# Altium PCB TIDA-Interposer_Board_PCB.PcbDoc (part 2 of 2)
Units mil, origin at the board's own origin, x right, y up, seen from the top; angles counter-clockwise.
Board outline 4000 x 3600 mil, 4 copper layers (Top Layer, GND, PWR, Bottom Layer), stack 5.48 mil thick; 55 components, 24 nets, 133 pads, 140 vias.
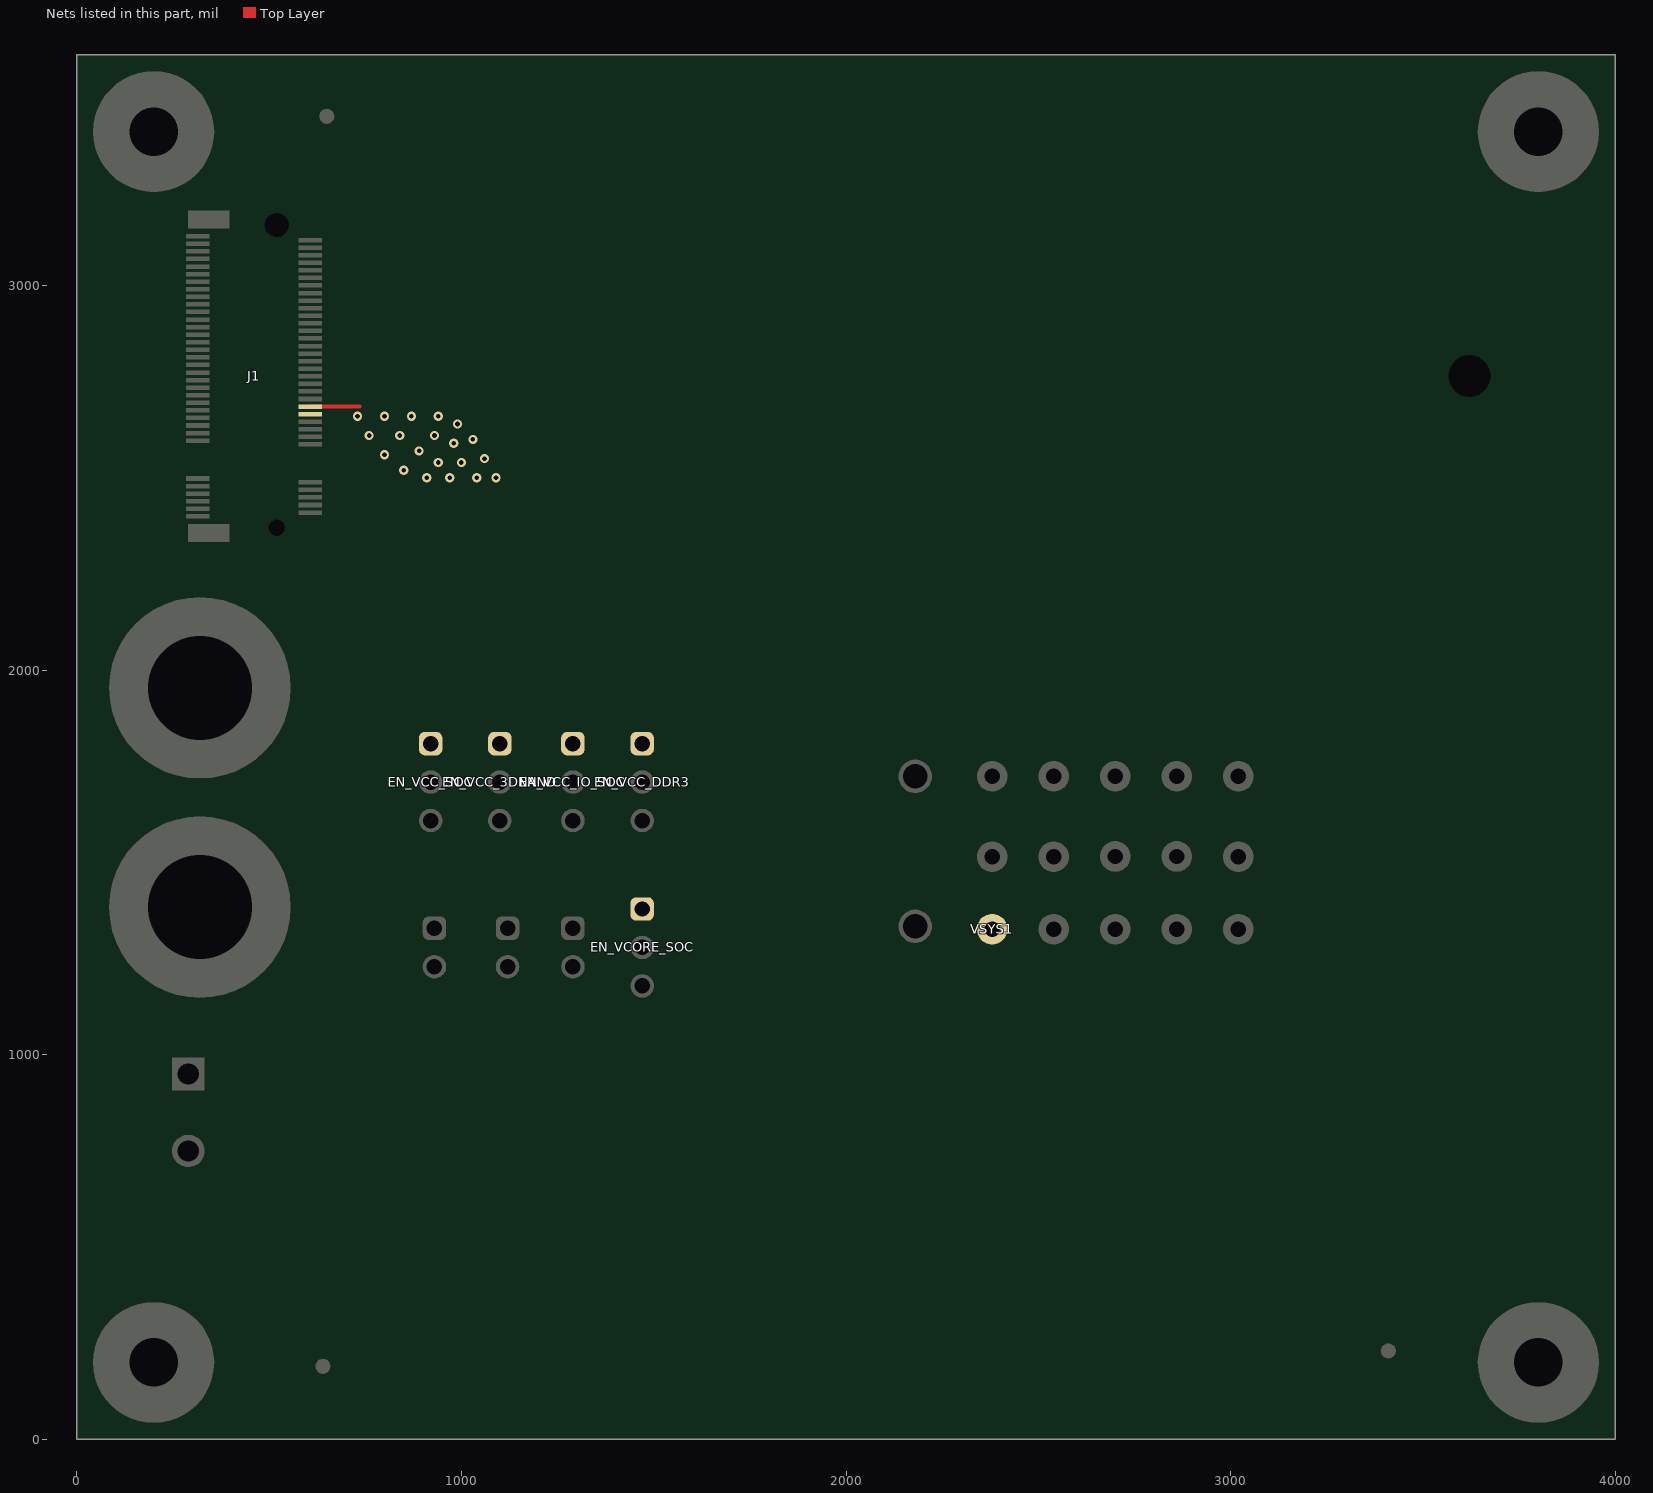
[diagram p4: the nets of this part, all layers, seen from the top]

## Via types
v1: diameter 24, hole 12, Top Layer to Bottom Layer, 140 vias

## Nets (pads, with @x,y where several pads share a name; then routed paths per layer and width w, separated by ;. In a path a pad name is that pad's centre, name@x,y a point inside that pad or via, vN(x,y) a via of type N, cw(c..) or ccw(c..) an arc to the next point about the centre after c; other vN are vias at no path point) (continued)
VSYS: EN_VCC_3DNAND.1 EN_VCC_DDR3.1 EN_VCC_IO_SOC.1 EN_VCC_SOC.1 EN_VCORE_SOC.1 J1.28 J1.30 VSYS1.1 | length 127.1
  Top Layer w10: J1.30@607.6,2685.26 734.74,2685.26
  other v1: 910,2500 970,2500 1040,2500 1090,2500 850,2520 940,2540 1000,2540 1060,2550 800,2560 890,2570 980,2590 1030,2600 760,2610 840,2610 930,2610 990,2640 730,2660 800,2660 870,2660 940,2660
pads on no net: FID1.1 FID2.1 FID3.1 H1.1 H2.1 H3.1 H4.1 H5.0 H6.0 H7.0 H8.0 J1.MH1 J1.MH2 J1.MP1 J1.MP2 SH-J1.0 SH-J2.0 SH-J3.0 SH-J4.0 SH-J5.0 SH-J6.0 SH-J7.0 SH-J8.0

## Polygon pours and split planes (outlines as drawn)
GND on Top Layer "TOP_LAYER_GND_P032" (solid, remove dead copper, pour order 32): 92.87,3442.87 190,3540 3840,3540 3940,3440 3940,160 3860,80 230,80 81.79,228.21
VCC_IO_3DNAND on Top Layer "TOP_LAYER_VCC_IO_3DNAND_P028" (solid, remove dead copper, pour order 28): 390,2880 400,2870 370,2840 270,2840 270,2890 280,2900 370,2900
VCC_3DNAND on Top Layer "TOP_LAYER_VCC_3DNAND_P026" (solid, remove dead copper, pour order 26): 710.54,2980.54 708.18,2978.18 658.18,2978.18 650,2970 410,2970 380,2940 280,2940 270,2950 270,3010 273.84,3013.84 371.26,3013.84 387.42,3030 560,3030 567.74,3022.26 710.87,3022.26 730,3003.13 730,3000
VAUX on Top Layer "TOP_LAYER_VAUX_P012" (solid, remove dead copper, pour order 12): 200,2710 250,2710 276,2684 350,2684 360,2684 364.29,2679.71 364.29,2652.47 292.47,2652.47 290,2650 260,2620 190,2620 180,2630 180,2690
VSYS on Top Layer "TOP_LAYER_VSYS_P006" (solid, remove dead copper, pour order 6): 2472.49,1747.51 2472.49,1286.49 2440,1254 1990,1254 1326,1254 810,1770 810,2504 652.2,2661.8 572.2,2661.8 570,2664 570,2684 575.04,2689.04 834.96,2689.04 1530.96,2689.04
VIN on Top Layer "TOP_LAYER_VIN_P014" (solid, remove dead copper, pour order 14): 1037.86,1493.17 1302.19,1228.84 2896.81,1230.81 2936,1270 2936,1376 2984,1424 3090,1424 3140,1374 3140,1104 2936,900 880,900 126,1654 58.85,1721.15 58.85,2488.85 189.32,2619.31 255.82,2619.31 555.31,2619.31 570,2634 630,2634 770,2494 770,1756.97
GND on Bottom Layer "BOTTOM_LAYER_GND_P016" (solid, remove dead copper, pour order 16): 59.74,3356.21 253.52,3550 3870,3550 3940,3480 3940,194.23 3795.77,50 200,50 59.74,190.26
VAUX on Bottom Layer "BOTTOM_LAYER_VAUX_P010" (solid, remove dead copper, pour order 10): 252,642 1622,642 1688,692 2450,1454 2450,1550 2376,1624 2250,1624 1526,900 916.36,900 830,995 830,2070 360,2540 360,2695.1 344.38,2710.72 191.42,2710.72 179.61,2698.91 179.61,2470.39 200,2450 590,2060 590,1110 490,1010 240,1010 170,940 170,724
GND on GND "GND_GND_P018" (solid, remove dead copper, pour order 18): 63.01,3413.01 190,3540 3840,3540 3940,3440 3940,160 3860,80 230,80 52.13,257.87
VSYS on PWR "PWR_VSYS_P020" (solid, remove dead copper, pour order 20): 2472.49,1821.52 2472.49,1322.49 2350,1200 1380,1200 810,1770 810,2280.56 440,2650.56 440,2820 680,3060 1234,3060
VIN on PWR "PWR_VIN_P022" (solid, remove dead copper, pour order 22): 144,2634 59.57,2549.57 59.57,880.43 260,680 3070,680 3220,830 3220,1400 3180,1440 2990,1440 2950,1400 2950,1284 2870,1204 2120,1204 1331.48,1204 770,1756.97 770,2295.28 431.28,2634

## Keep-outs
Keep-Out Layer:
  the board outline again, w10
  text ".Layer_Name" at 577,-1254.49 h60

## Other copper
Top Layer:
  pour cut-out: 2989.81,1677.84 2989.81,1740.19 2890,1840 2880,1840 2870,1830 2870,1770 2910,1730 2910,1697.09 2890.75,1677.84 2890.75,1669.25 2958.29,1601.71
  text ".Layer_Name" at 577,-1254.49 h60
GND:
  text "'.Layer_Name'" at 780,-1230 h60
PWR:
  text "'.Layer_Name'" at 1100,-1230 h60
Bottom Layer:
  pour cut-out: 860,1740 920,1740 960,1700 960,1370 950,1360 909.01,1360 850,1419.01 850,1730
  pour cut-out: 470,2460 510,2500 520,2500 840,2180 840,2110 820,2110
  text ".Layer_Name" at 577,-1254.49 h60

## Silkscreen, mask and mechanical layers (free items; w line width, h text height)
Top Overlay:
  lines w6: 1860,1910 2030,1910 2080,1860 2080,1630 2100,1610 3060,1610 3100,1570 3100,1490 3050,1440 1750,1440 1690,1500 1690,1740 1690,1860 1740,1910 1870,1910 ; 2400,1400 3090,1400 3120,1430 3120,1590 3160,1630 3420,1630 3450,1600 3450,1260 3440,1250 2310,1250 2300,1260 2300,1390 2310,1400 2410,1400
  text "VIN" at 600,1900 h40
  text "GND" at 610,1290 h40
  text "VAUX" at 500,910 h40
  text "'.PRJ_Title'" at 2010,770 h60
  text "GND" at 500,710 h40
  text "'.PRJ_Number' .PCB_Rev" at 2210,600 h108.27
  text ".Layer_Name" at 577,-1254.49 h60
Bottom Overlay:
  text ".Layer_Name" at 577,-1254.49 h60
Top Paste:
  text ".Layer_Name" at 577,-1254.49 h60
Bottom Paste:
  text ".Layer_Name" at 577,-1254.49 h60
Top Solder:
  text ".Layer_Name" at 577,-1254.49 h60
  text ".Layer_Name" at 577,-1254.49 h60
Bottom Solder:
  text ".Layer_Name" at 577,-1254.49 h60
Drill Guide:
  text ".Layer_Name" at 577,-1254.49 h60
M1 Board Outline:
  the board outline again, w10
M2 Board Dimensions:
  rectangle: 0,-671 125,-546
  rectangle: 125,-796 500,-671
  lines w7: 0,-671 1000,-671 ; 125,-796 125,-546 ; 250,-796 250,-546 ; 500,-796 500,-546 ; 750,-796 750,-546 ; 0,-796 1000,-796 1000,-546 0,-546 0,-796
M3 3D STEP Top:
  text ".Layer_Name" at 577,-1254.49 h60
M4 3D STEP Bottom:
  text ".Layer_Name" at 577,-1254.49 h60
M5 Assembly Top:
  lines w10: -292,-1326.17 6308,-1326.17 ; -292,-1122.83 6310,-1122.83 ; -292,-919.5 -292,-1529.5 3713,-1529.5 6310,-1529.5 6310,-919.5 -291.5,-919.5 -291.5,-1529.5 1284,-1529.5 ; 2173,-1529.5 2173,-919.5 ; 3440,-1122.83 3440,-919.5 ; 4280,-1122.83 4280,-919.5 ; 4902,-1536 4902,-1333.17
  text "COMPONENTS MARKED 'DNP' SHOULD NOT BE POPULATED." at 1153.5,-714.5 h60
  text "ASSEMBLY VARIANT:" at 1153,-830 h60
  text ".VariantName" at 2189,-830 h60
  text "PCB VIEWED FROM TOP SIDE" at -228.5,-1051.67 h60
  text "BOARD #:" at 2248,-1051.67 h60
  text ".PRJ_Number" at 2793.5,-1051.67 h60
  text "REV:" at 3638,-1051.67 h60
  text ".PCB_Rev" at 3929.5,-1051.67 h60
  text "SVN REV:" at 4476,-1051.67 h60
  text ".VersionControl_RevNumber" at 4982,-1051.67 h60
  text "TID #:" at 2248,-1255 h60
  text ".TID" at 2793.5,-1255 h60
  text "'.Layer_Name'" at 400,-1260 h60
  text "PLOT NAME =" at -260,-1450 h50
  text ".plot_File_Name" at 310,-1450 h43
  text "GENERATED    :" at 2250,-1460.34 h60
  text ".Print_Date" at 3119.5,-1460.34 h60
  text ".Print_Time" at 3848.5,-1460.34 h60
  text "TEXAS INSTRUMENTS" at 5113,-1460.34 h60
M6 Assembly Bottom:
  lines w10: -292.5,-1123.33 6309.5,-1123.33 ; -290.5,-1326.67 6309.5,-1326.67 ; 1115.5,-1536.5 1115.5,-1333.67 ; 1737.5,-1123.33 1737.5,-920 ; 2577.5,-1123.33 2577.5,-920 ; 3844.5,-1530 3844.5,-920 ; 4733.5,-1530 6309,-1530 6309,-920 -292.5,-920 -292.5,-1530 2304.5,-1530 6309.5,-1530 6309.5,-920
  text "COMPONENTS MARKED 'DNP' SHOULD NOT BE POPULATED." at 6102,-714 h60
  text ".VariantName" at 5058,-830 h60
  text "ASSEMBLY VARIANT:" at 6097,-830 h60
  text ".VersionControl_RevNumber" at 1035.5,-1052.17 h60
  text "SVN REV:" at 1541.5,-1052.17 h60
  text ".PCB_Rev" at 2088,-1052.17 h60
  text "REV:" at 2379.5,-1052.17 h60
  text ".PRJ_Number" at 3224,-1052.17 h60
  text "BOARD #:" at 3769.5,-1052.17 h60
  text "PCB VIEWED FROM BOTTOM SIDE" at 6246,-1052.17 h60
  text "'.Layer_Name'" at 5690,-1240 h60
  text ".TID" at 3224,-1255.5 h60
  text "TID #:" at 3769.5,-1255.5 h60
  text "TEXAS INSTRUMENTS" at 904.5,-1460.84 h60
  text ".Print_Time" at 2169,-1460.84 h60
  text ".Print_Date" at 2898,-1460.84 h60
  text "GENERATED    :" at 3767.5,-1460.84 h60
  text ".plot_File_Name" at 5440.5,-1460.84 h60
  text "PLOT NAME =" at 6246,-1460.84 h60
M9 Title Sheet:
  drawing of 57 lines, arcs and shapes, not listed
  text "1" at 739.84,7640.5 h70
  text "2" at 3235.5,7640.5 h70
  text "3" at 5724.84,7640.5 h70
  text "4" at 8231.51,7640.5 h70
  text "5" at 10730.5,7640.5 h70
  text "6" at 13235.5,7640.5 h70
  text "A" at -416.5,6497.5 h70
  text "A" at 14383.5,6497.5 h70
  text "B" at -416.5,4117.5 h70
  text "B" at 14383.5,4117.5 h70
  text "C" at -416.5,1742.5 h70
  text "C" at 14383.5,1742.5 h70
  text "PROJECT TITLE:" at 11343.5,-118.5 h45
  text ".PRJ_Title" at 11393.5,-251.83 h70
  text "DESIGNED FOR:" at 11343.5,-419.5 h45
  text ".PRJ_Customer" at 11393.5,-559.5 h70
  text "D" at -416.5,-627.5 h70
  text "D" at 14383.5,-627.5 h70
  text "FILE NAME:" at 11343.5,-719.5 h45
  text ".PCB_File_Name_No_Path" at 11393.5,-839.5 h70
  text "Texas Instruments (TI) and/or its licensors do not warrant the accuracy or completeness of this specification" at 6374,-1001.34 h45
  text "ENGINEER:" at 11343.5,-1009.5 h45
  text "LAYOUT BY:" at 12848.5,-1009.5 h45
  text "or any information contained therein. TI and/or its licensors do not warrant that this design will meet" at 6329.01,-1114 h45
  text ".PRJ_Engineer" at 11393.5,-1164.49 h70
  text ".PCB_Layout" at 12899,-1164.49 h70
  text "the specifications, will be suitable for your application or fit for any particular purpose, or will operate in" at 6329.01,-1226.67 h45
  text "ALTIUM DESIGNER VERSION:" at 12848.5,-1319.5 h45
  text "an implementation. TI and/or its licensors do not warrant that the design is production worthy. You should" at 6329.01,-1339.33 h45
  text "completely validate and test your design implementation to confirm the system functionality for your application." at 6374,-1452 h45
  text ".print_Scale" at 11393.5,-1452.83 h70
  text ".Application_BuildNumber" at 12899,-1452.83 h70
  text "1" at 739.84,-1659.5 h70
  text "2" at 3235.5,-1659.5 h70
  text "3" at 5724.84,-1659.5 h70
  text "4" at 8231.51,-1659.5 h70
  text "5" at 10730.5,-1659.5 h70
  text "6" at 13235.5,-1659.5 h70
M10 Fab Notes:
  drawing of 189 lines, arcs and shapes, not listed
  text "DESIGN INFORMATION" at 12382.02,5960.17 h60
  text "MIN. TRACK WIDTH:" at 11737.46,5828.05 h60
  text "10" at 12833.7,5828.05 h60
  text "MIL" at 12988.46,5828.05 h60
  text "MIN. CLEARANCE:" at 11737.46,5703.92 h60
  text "0.2" at 12773.7,5703.93 h60
  text "mm" at 12988.46,5703.92 h60
  text "MIN. VIA PAD SIZE:" at 11737.46,5579.8 h60
  text "24" at 12803.71,5579.8 h60
  text "MIL" at 12988.46,5579.8 h60
  text "0.05mm (2MIL)" at 12432.46,5449.9 h60
  text "MINIMUM ANNULAR RING" at 11408.23,5441.67 h60
  text "EXTERNAL" at 13140.46,5441.67 h60
  text "PER" at 11608.23,5331.55 h60
  text "IPC-D-275 CLASS 2 LEVEL C" at 11828.23,5331.54 h60
  text "MIL, HOLES" at 13316.46,5231.07 h60
  text "+/-" at 12924,5222.48 h60
  text "+/-" at 13778,5222.48 h60
  text "REGISTRATION TOLERANCES:" at 11408.23,5221.42 h60
  text "METAL" at 12608,5221.42 h60
  text "5" at 13184.2,5221.42 h60
  text "3" at 14017.2,5221.42 h60
  text "MIL" at 14133.46,5221.42 h60
  text "HOLE SIZE TOLERANCE (UNLESS OTHERWISE SPECIFIED):" at 11408.23,5123.1 h60
  text "+/-" at 13778,5120.23 h60
  text "3" at 14017.2,5119.17 h60
  text "MIL" at 14133.46,5119.17 h60
  text "MATERIAL:" at 11333.46,4981.52 h60
  text "FR-4 High Tg" at 12319.9,4853 h60
  text "X" at 12175.46,4845.01 h60
  text "FR-408" at 11754.46,4840.49 h60
  text "OTHER" at 13242.46,4840.49 h60
  text "62 MIL (1.6mm) +/-10%" at 12074.56,4697.46 h60
  text "X" at 11954.46,4692.06 h60
  text "THICKNESS:" at 11408.23,4689.24 h60
  text "OTHER" at 13359.46,4689.24 h60
  text "TOLERANCE:" at 11408.23,4550.92 h60
  text "X" at 12256.46,4550.92 h60
  text "ANSI IPC-6012 TYPE 3 CLASS 2" at 12434.48,4550.92 h60
  text "OTHER +/-" at 12434.46,4406.73 h60
  text "BOW & TWIST:" at 11408.23,4261.54 h60
  text "X" at 12256.46,4261.54 h60
  text "ANSI IPC-6012 TYPE 3 CLASS 2" at 12434.48,4261.54 h60
  text "FAB NOTE:" at 6063.74,4162.19 h60
  text "OTHER +/-" at 12434.46,4114.85 h60
  text "1.THIS IS NOT IMPEDANCE CONTROL BOARD" at 6130,4020 h60
  text "DRILLING:" at 11333.46,3984.23 h60
  text "2. BOARD THICKNESS IS 1.6MM, DIELCTRIC THICKENSS CAN BE ADJUSTED BY FAB VENDOR." at 6120,3910 h60
  text "NC_DRILL FILES" at 13094.46,3879.04 h60
  text "REFERENCE:" at 11408.23,3875.1 h60
  text "X" at 12065.46,3875.01 h60
  text "AS SHOWN" at 12243.46,3875.1 h60
  text "X" at 12966.46,3875.1 h60
  text "OTHER" at 13392.46,3732.85 h60
  text "PTH COPPER THICKNESS:" at 11407.91,3729.32 h60
  text "X" at 12547.14,3729.32 h60
  text "20-30 um" at 12675.14,3729.32 h60
  text "3. VENDER MAY ADJEST SOLDERMASK WHEREVER SOLDERMASK PADS ARE SAME SIZE (1:1) AS PER  /    THE MANUFACTURING CAPABILITIES AND ALL OTHER SOLDERMASK PADS SHALL NOT BE MODIFIED." at 5370,3650 h60
  text "BOARD FINISH:" at 11333.46,3581.73 h60
  text "SILKSCREEN:" at 11488.68,3471.6 h60
  text "X" at 12446.46,3471.6 h60
  text "TOP" at 12563.46,3471.6 h60
  text "BOTTOM" at 13074.46,3471.6 h60
  text "4. PROVIDE NO ADJECENT COPPER IS EXPOSED AND NO CONFLICT IS PRODUCED /     WITH  ANY STATED \"VIA TENTING/COVERING\" REQUIREMENTS." at 6110,3430 h60
  text "SILKSCREEN COLOR:" at 11488.68,3316.41 h60
  text "X" at 12445.46,3316.41 h60
  text "WHITE" at 12563.46,3316.41 h60
  text "OTHER" at 13074.46,3316.41 h60
  text "X" at 12576.46,3172.96 h60
  text "GREEN" at 12694.46,3172.96 h60
  text "OTHER" at 13312.46,3172.96 h60
  text "SOLDER RESIST COLOR:" at 11488.68,3166.1 h60
  text "X" at 12576.46,3018.71 h60
  text "MATTE" at 12694.46,3018.71 h60
  text "SEMI-GLOSS" at 13312,3018.07 h60
  text "IMMERSION GOLD (ENIG)" at 12394.46,2845.94 h60
  text "ENEPIG" at 13732,2838.72 h60
  text "SURFACE FINISH:" at 11333.46,2837.72 h60
  text "X" at 12216.46,2837.72 h60
  text "IMM. TIN/SILVER OR EQUIV" at 11663,2700.4 h60
  text "OTHER" at 13094.46,2696.47 h60
  text "ARRAY/PANEL:" at 11333.46,2541.09 h60
  text "CUT AND TRIM PER M1 BOARD OUTLINE" at 12394.46,2532.87 h60
  text "X" at 12210,2530 h60
  text "N.C. ROUTE" at 12394.46,2396.9 h60
  text "V. SCORE" at 13260.46,2396.9 h60
  text "CERTIFICATION:" at 11333.46,2267.77 h60
  text "MATERIALS AND WORKMANSHIP FOR ALL PCBS" at 12058.46,2267.77 h60
  text "TO MEET OR EXCEED THE REQUIREMENTS OF:" at 12058.46,2173.71 h60
  text "X" at 11695.97,2045.08 h60
  text "ANSI IPC-A-600F CLASS ->" at 11823.96,2045.08 h60
  text "X" at 13471.97,2045.08 h60
  text "2" at 13581.96,2045.08 h60
  text "1" at 13266.96,2043.58 h60
  text "3" at 13935.96,2043.58 h60
  text "X" at 12507.97,1897.39 h60
  text "RoHS" at 12635.96,1897.39 h60
  text "OTHER" at 13280.36,1897.39 h60
  text "PER ORDER" at 13677.42,1897.39 h60
  text "ALL BOARDS MUST MEET OR EXCEED UL94-V0 REQUIREMENTS." at 11361,1743.57 h60
  text "PCB MUST BEAR THE UL94V-0 UL REGISTERED MATERIAL ID NUMBER" at 11361,1627.5 h60
  text "ADDITIONAL REQUIREMENTS:" at 11333.46,1458.08 h60
  text "MICROSECTION:" at 11408.23,1350.95 h60
  text "YES" at 12313.96,1350.95 h60
  text "REQUIRED" at 13175.46,1206.62 h60
  text "BARE BOARD ELEC. TEST:" at 11408.23,1203.76 h60
  text "NONE" at 12713.96,1203.76 h60
  text "X" at 13057.46,1203.76 h60
  text "PER ORDER" at 13767.46,1203.76 h60
  text "XX MIL VIAS REQUIRE NON-CONDUCTIVE FILL AND PLANARIZE" at 11576.38,998.82 h59
  text "XX MIL VIAS REQUIRE CONDUCTIVE FILL AND PLANARIZE" at 11584.38,894.84 h60
  text "OUTER XX MIL TRACES REQUIRE 50 OHM SINGLE-ENDED IMPEDANCE" at 11583.39,731.46 h58
  text "LAYER 2 & 3 (INNER LAYERS) XX MIL WIDE, XX MIL SPACE / TRACES REQUIRE 100 OHM DIFFERENTIAL IMPEDANCE" at 11575.39,495.74 h60
M11 Gerber Information:
  lines w10: -292,-1326.17 6308,-1326.17 ; -292,-1122.83 6310,-1122.83 ; -292,-919.5 -292,-1529.5 3713,-1529.5 6310,-1529.5 6310,-919.5 -291.5,-919.5 -291.5,-1529.5 1284,-1529.5 ; 2173,-1529.5 2173,-919.5 ; 3440,-1122.83 3440,-919.5 ; 4280,-1122.83 4280,-919.5 ; 4902,-1536 4902,-1333.17
  text "ALL ARTWORK VIEWED FROM TOP SIDE" at -228.5,-1051.67 h60
  text "BOARD #:" at 2248,-1051.67 h60
  text ".PRJ_Number" at 2793.5,-1051.67 h60
  text "REV:" at 3638,-1051.67 h60
  text ".PCB_Rev" at 3929.5,-1051.67 h60
  text "SVN REV:" at 4476,-1051.67 h60
  text ".VersionControl_RevNumber" at 4982,-1051.67 h60
  text "LAYER NAME =" at -228.5,-1254.49 h60
  text "TID #:" at 2248,-1255 h60
  text ".TID" at 2793.5,-1255 h60
  text "PLOT NAME =" at -260,-1440 h50
  text ".plot_File_Name" at 320,-1440 h42
  text "GENERATED    :" at 2250,-1460.34 h60
  text ".Print_Date" at 3119.5,-1460.34 h60
  text ".Print_Time" at 3848.5,-1460.34 h60
  text "TEXAS INSTRUMENTS" at 5113,-1460.34 h60
M12 Stackup:
  drawing of 269 lines, arcs and shapes, not listed
  text "Layer" at 9797.84,7434 h60
  text "Name" at 10207.76,7434 h60
  text "Material" at 11067.52,7434 h60
  text "Thickness" at 11927.29,7434 h60
  text "Constant" at 12577.12,7434 h60
  text "Board Layer Stack" at 13146.99,7434 h60
  text "1" at 9797.84,7314 h60
  text "Top Overlay" at 10207.76,7314 h60
  text "2" at 9797.84,7194 h60
  text "Top Solder" at 10207.76,7194 h60
  text "Solder Resist" at 11067.52,7194 h60
  text "0.80mil" at 11927.29,7194 h60
  text "0" at 12577.12,7194 h60
  text "3" at 9797.84,7074 h60
  text "Top Layer" at 10207.76,7074 h60
  text "Copper" at 11067.52,7074 h60
  text "1.37mil" at 11927.29,7074 h60
  text "4" at 9797.84,6954 h60
  text "Dielectric 3" at 10207.76,6954 h60
  text "FR-4 High Tg" at 11067.52,6954 h60
  text "0" at 12577.12,6954 h60
  text "5" at 9797.84,6834 h60
  text "GND" at 10207.76,6834 h60
  text "Copper" at 11067.52,6834 h60
  text "1.37mil" at 11927.29,6834 h60
  text "6" at 9797.84,6714 h60
  text "Dielectric 2" at 10207.76,6714 h60
  text "FR-4 High Tg" at 11067.52,6714 h60
  text "0" at 12577.12,6714 h60
  text "7" at 9797.84,6594 h60
  text "PWR" at 10207.76,6594 h60
  text "Copper" at 11067.52,6594 h60
  text "1.37mil" at 11927.29,6594 h60
  text "8" at 9797.84,6474 h60
  text "Dielectric1" at 10207.76,6474 h60
  text "FR-4 High Tg" at 11067.52,6474 h60
  text "0" at 12577.12,6474 h60
  text "9" at 9797.84,6354 h60
  text "Bottom Layer" at 10207.76,6354 h60
  text "Copper" at 11067.52,6354 h60
  text "1.37mil" at 11927.29,6354 h60
  text "10" at 9797.84,6234 h60
  text "Bottom Solder" at 10207.76,6234 h60
  text "Solder Resist" at 11067.52,6234 h60
  text "0.80mil" at 11927.29,6234 h60
  text "0" at 12577.12,6234 h60
M13 Component Bodies Top:
  text ".Layer_Name" at 577,-1254.49 h60
M14 Component Bodies Bottom:
  text ".Layer_Name" at 577,-1254.49 h60
M15 Courtyards Top:
  text ".Layer_Name" at 577,-1254.49 h60
M16 Courtyards Bottom:
  text ".Layer_Name" at 577,-1254.49 h60
Drill Drawing:
  circle w10: c5397.53,2633.45 r20.26
  circle w10: c5397.53,2633.45 r33.76
  circle w10: c5397.53,1873.76 r33.76
  lines w10: 5363.77,1553.01 5380.65,1553.01 5397.53,1536.12 5414.41,1553.01 5431.3,1553.01 5414.41,1569.89 5431.3,1586.77 5414.41,1586.77 5397.53,1603.65 5380.65,1586.77 5363.77,1586.77 5380.65,1569.89 5363.77,1553.01 ; 5363.77,1688.06 5363.77,1704.94 5380.65,1721.83 5363.77,1738.71 5363.77,1755.59 5380.65,1755.59 5397.53,1738.71 5414.41,1755.59 5431.3,1755.59 5431.3,1738.71 5414.41,1721.83 5431.3,1704.94 5431.3,1688.06 5414.41,1688.06 5397.53,1704.94 5380.65,1688.06 5363.77,1688.06 ; 5363.77,1991.94 5397.53,2008.82 5431.3,1991.94 5414.41,2025.7 5431.3,2059.47 5397.53,2042.58 5363.77,2059.47 5380.65,2025.7 5363.77,1991.94 ; 5363.77,2177.64 5397.53,2143.88 5431.3,2177.64 5397.53,2211.4 5363.77,2177.64 ; 5363.77,2312.7 5380.65,2312.7 5397.53,2295.81 5414.41,2312.7 5431.3,2312.7 5414.41,2329.58 5431.3,2346.46 5414.41,2346.46 5397.53,2363.34 5380.65,2346.46 5363.77,2346.46 5380.65,2329.58 5363.77,2312.7 ; 5363.77,2515.28 5431.3,2515.28 5397.53,2447.75 5363.77,2515.28 ; 5363.77,2751.63 5431.3,2751.63 5431.3,2819.16 5363.77,2819.16 5363.77,2751.63 ; 5363.77,2903.57 5363.77,2920.45 5380.65,2937.33 5363.77,2954.21 5363.77,2971.09 5380.65,2971.09 5397.53,2954.21 5414.41,2971.09 5431.3,2971.09 5431.3,2954.21 5414.41,2937.33 5431.3,2920.45 5431.3,2903.57 5414.41,2903.57 5397.53,2920.45 5380.65,2903.57 5363.77,2903.57 ; 5377.27,2319.45 5387.4,2319.45 5397.53,2309.32 5407.66,2319.45 5417.79,2319.45 5407.66,2329.58 5417.79,2339.71 5407.66,2339.71 5397.53,2349.84 5387.4,2339.71 5377.27,2339.71 5387.4,2329.58 5377.27,2319.45 ; 5377.27,2917.07 5377.27,2927.2 5387.4,2937.33 5377.27,2947.46 5377.27,2957.59 5387.4,2957.59 5397.53,2947.46 5407.66,2957.59 5417.79,2957.59 5417.79,2947.46 5407.66,2937.33 5417.79,2927.2 5417.79,2917.07 5407.66,2917.07 5397.53,2927.2 5387.4,2917.07 5377.27,2917.07
  lines w15: 5303.24,1490.54 10451.54,1490.54 ; 5303.24,3009.92 10451.54,3009.92 ; 5860.82,1338.6 5860.82,3161.86 ; 6458.03,1338.6 6458.03,3161.86 ; 7632.42,1338.6 7632.42,3161.86 ; 8144.42,1338.6 8144.42,3161.86 ; 8887.29,1338.6 8887.29,3161.86 ; 5303.24,1338.6 10451.54,1338.6 10451.54,3161.86 5303.24,3161.86 5303.24,1338.6
  text "Symbol" at 5394.41,3055.5 h72.93
  text "Count" at 5906.41,3055.5 h72.93
  text "Hole Size" at 6503.61,3055.5 h72.93
  text "Plated" at 7678,3055.5 h72.93
  text "Hole Type" at 8190,3055.5 h72.93
  text "Drill Layer Pair" at 8932.87,3055.5 h72.93
  text "140" at 5906.41,2903.57 h60.78
  text "12.00mil (0.305mm)" at 6503.61,2903.57 h60.78
  text "PTH" at 7678,2903.57 h60.78
  text "Round" at 8190,2903.57 h60.78
  text "Top Layer - Bottom Layer" at 8932.87,2903.57 h60.78
  text "15" at 5906.41,2751.63 h60.78
  text "40.00mil (1.016mm)" at 6503.61,2751.63 h60.78
  text "PTH" at 7678,2751.63 h60.78
  text "Round" at 8190,2751.63 h60.78
  text "Top Layer - Bottom Layer" at 8932.87,2751.63 h60.78
  text "21" at 5906.41,2599.69 h60.78
  text "40.16mil (1.020mm)" at 6503.61,2599.69 h60.78
  text "PTH" at 7678,2599.69 h60.78
  text "Round" at 8190,2599.69 h60.78
  text "Top Layer - Bottom Layer" at 8932.87,2599.69 h60.78
  text "1" at 5906.41,2447.75 h60.78
  text "43.31mil (1.100mm)" at 6503.61,2447.75 h60.78
  text "NPTH" at 7678,2447.75 h60.78
  text "Round" at 8190,2447.75 h60.78
  text "Top Layer - Bottom Layer" at 8932.87,2447.75 h60.78
  text "2" at 5906.41,2295.81 h60.78
  text "55.12mil (1.400mm)" at 6503.61,2295.81 h60.78
  text "PTH" at 7678,2295.81 h60.78
  text "Round" at 8190,2295.81 h60.78
  text "Top Layer - Bottom Layer" at 8932.87,2295.81 h60.78
  text "1" at 5906.41,2143.88 h60.78
  text "62.99mil (1.600mm)" at 6503.61,2143.88 h60.78
  text "NPTH" at 7678,2143.88 h60.78
  text "Round" at 8190,2143.88 h60.78
  text "Top Layer - Bottom Layer" at 8932.87,2143.88 h60.78
  text "2" at 5906.41,1991.94 h60.78
  text "63.00mil (1.600mm)" at 6503.61,1991.94 h60.78
  text "PTH" at 7678,1991.94 h60.78
  text "Round" at 8190,1991.94 h60.78
  text "Top Layer - Bottom Layer" at 8932.87,1991.94 h60.78
  text "1" at 5906.41,1840 h60.78
  text "110.00mil (2.794mm)" at 6503.61,1840 h60.78
  text "NPTH" at 7678,1840 h60.78
  text "Round" at 8190,1840 h60.78
  text "Top Layer - Bottom Layer" at 8932.87,1840 h60.78
  text "4" at 5906.41,1688.06 h60.78
  text "125.98mil (3.200mm)" at 6503.61,1688.06 h60.78
  text "PTH" at 7678,1688.06 h60.78
  text "Round" at 8190,1688.06 h60.78
  text "Top Layer - Bottom Layer" at 8932.87,1688.06 h60.78
  text "2" at 5906.41,1536.12 h60.78
  text "270.00mil (6.858mm)" at 6503.61,1536.12 h60.78
  text "PTH" at 7678,1536.12 h60.78
  text "Round" at 8190,1536.12 h60.78
  text "Top Layer - Bottom Layer" at 8932.87,1536.12 h60.78
  text "189 Total" at 5906.41,1384.19 h60.78
  text "Drill tolerances:" at 5513,1130 h40
  text "For 12 mil drill via +0/-12 mil" at 5513,1057.33 h40
  text "For PTH drill +/- 3 mil" at 5513,984.67 h40
  text "For NPTH drill +/- 2 mil" at 5513,912 h40
  text ".Layer_Name" at 577,-1254.49 h60
M17 Embedded Cavity:
  text ".Layer_Name" at 577,-1254.49 h60
M18 Embedded Assembly:
  text ".Layer_Name" at 577,-1254.49 h60
M19 Embedded Keepout:
  text ".Layer_Name" at 577,-1254.49 h60
Mechanical 20:
  lines w5: 665.67,2331.56 3609.61,2331.56 3610,2331.95 3610,2710.8 ; 665.67,3197.7 3610,3197.7 3610,3197.31 3610,2818.46 ; 3609.96,2710.8 cw(c3621.25,2764.63) 3609.96,2818.46

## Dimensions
3610,3197.7 to 3609.61,2331.56 on M16 Courtyards Bottom
0,-796 to 1000,-796 on M2 Board Dimensions
4000,3600 to 0,3600 on M2 Board Dimensions
4000,3600 to 4000,0 on M2 Board Dimensions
